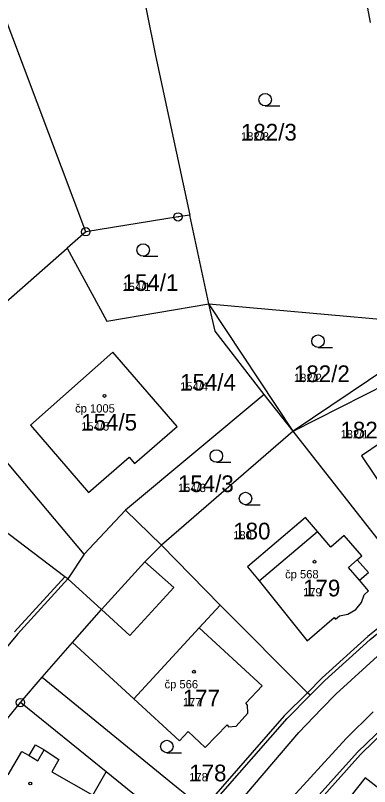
# Model space of a CAD drawing. Extents: x -763628 to -761565, y -976033 to -973833.
# Drawn here: x -762655.5 to -762613, y -974691 to -974598.6 of the extents above; entities that cross this region are included whole.
import ezdxf

# ---------------------------------------------------------------- set-up
doc = ezdxf.new("R2010")
doc.units = 0
for name, color, linetype in [('KN_cisla parcel 1000', 7, 'Continuous'), ('KN_cisla parcel 500', 7, 'Continuous'), ('KN_cisla popisna 500', 7, 'Continuous'), ('KN_hranice parcel', 7, 'Continuous'), ('KN_vnitrni kresba parcel', 7, 'Continuous'), ('KN_znacky bodu BP', 7, 'Continuous'), ('KN_znacky budov', 7, 'Continuous'), ('KN_znacky kultur', 7, 'Continuous')]:
    doc.layers.add(name, color=color, linetype=linetype)

msp = doc.modelspace()

# ---------------------------------------------------------------- linework, layer by layer
at = {"layer": 'KN_hranice parcel'}
for p, q in [((-762612.91, -974599.43), (-762618.76, -974568.2)), ((-762632.29, -974633.14), (-762634.57, -974622.51)), ((-762647.05, -974624.52), (-762649.29, -974626.49)), ((-762665.72, -974640.94), (-762649.29, -974626.49)), ((-762632.29, -974633.14), (-762603.39, -974635.73)), ((-762603.39, -974635.73), (-762622.2, -974648.42)), ((-762625.65, -974644.02), (-762642.29, -974657.86)), ((-762622.2, -974648.42), (-762625.65, -974644.02)), ((-762622.2, -974648.42), (-762637.97, -974662.06)), ((-762642.29, -974657.86), (-762647.23, -974663.13)), ((-762637.97, -974662.06), (-762642.29, -974657.86)), ((-762630.95, -974669.27), (-762637.97, -974662.06)), ((-762645.18, -974669.79), (-762649.21, -974666.12)), ((-762648.64, -974673.74), (-762645.18, -974669.79)), ((-762652.27, -974677.87), (-762648.64, -974673.74)), ((-762654.88, -974680.93), (-762652.27, -974677.87)), ((-762644.62, -974689.22), (-762654.88, -974680.93))]:
    msp.add_line(p, q, dxfattribs=at)
for points in [[(-762647.05, -974624.52), (-762657.34, -974597.25), (-762662.48, -974563.76)], [(-762618.76, -974568.2), (-762645.99, -974567.07), (-762638.7, -974603.41), (-762634.57, -974622.51)], [(-762634.57, -974622.51), (-762635.99, -974622.74), (-762647.05, -974624.52)], [(-762649.29, -974626.49), (-762644.53, -974635.22), (-762632.29, -974633.14)], [(-762625.65, -974644.02), (-762631.55, -974636.43), (-762632.29, -974633.14)], [(-762636.09, -974647.87), (-762643.79, -974638.96), (-762653.69, -974647.7), (-762646.7, -974655.78), (-762641.85, -974651.53), (-762641.2, -974652.28), (-762636.09, -974647.87)], [(-762647.23, -974663.13), (-762660.66, -974647.23), (-762665.72, -974640.94)], [(-762606.68, -974662.23), (-762604.57, -974660.79), (-762596.89, -974655.53), (-762599.81, -974651.16), (-762600.1, -974651.38), (-762604.11, -974645.61), (-762604.55, -974644.98), (-762613.98, -974651.38), (-762606.68, -974662.23)], [(-762649.21, -974666.12), (-762649.57, -974665.85), (-762673.44, -974647.74)], [(-762606.66, -974668.22), (-762606.94, -974667.88), (-762622.2, -974648.42)], [(-762619.26, -974660.44), (-762620.72, -974658.76), (-762627.64, -974664.67), (-762626.28, -974666.35), (-762620.5, -974673.52), (-762617.28, -974670.72), (-762617.12, -974670.92), (-762616.64, -974670.52), (-762615.65, -974670.32), (-762614.69, -974669.78), (-762613.98, -974668.93), (-762613.68, -974668.01), (-762613.14, -974667.53), (-762614.23, -974666.27), (-762613.17, -974665.35), (-762614.52, -974663.83), (-762613.97, -974663.36), (-762616.06, -974660.93), (-762617.68, -974662.3), (-762619.26, -974660.44)], [(-762637.97, -974662.06), (-762639.95, -974664.06), (-762645.18, -974669.79)], [(-762649.21, -974666.12), (-762655.24, -974672.73), (-762660.27, -974678.77), (-762663, -974682.24), (-762665.27, -974685.45)], [(-762620.14, -974680.06), (-762618.39, -974678.28), (-762612.95, -974673.38), (-762606.66, -974668.22)], [(-762648.64, -974673.74), (-762641.28, -974680.5), (-762635.82, -974685.52), (-762634.77, -974684.38), (-762632.73, -974686.32), (-762630.11, -974683.59), (-762629.92, -974683.82), (-762629, -974683.77), (-762627.61, -974682.22), (-762627.65, -974681.26), (-762627.84, -974681.02), (-762625.91, -974678.92), (-762633.44, -974671.98), (-762630.95, -974669.27)], [(-762620.14, -974680.06), (-762620.46, -974679.75), (-762630.95, -974669.27)], [(-762652.27, -974677.87), (-762636.16, -974691.01), (-762632.97, -974693.6), (-762632.63, -974693.89)], [(-762605.69, -974678.87), (-762611.21, -974683.7), (-762614.46, -974686.87), (-762623.69, -974697.16), (-762623.68, -974697.83), (-762623.61, -974701.35)], [(-762632.63, -974693.89), (-762622.92, -974682.83), (-762620.14, -974680.06)], [(-762663.53, -974693.31), (-762659.99, -974687.45), (-762657.52, -974684.12), (-762654.88, -974680.93)], [(-762663.53, -974693.31), (-762659.81, -974695.49), (-762651.09, -974700.6), (-762646.21, -974692.01), (-762644.62, -974689.22)], [(-762635.08, -974696.93), (-762635.43, -974696.65), (-762638.63, -974694.06), (-762644.62, -974689.22)], [(-762596.51, -974689.85), (-762600.44, -974694.72), (-762601.76, -974696.35), (-762603.78, -974694.73), (-762608.43, -974691), (-762610.68, -974689.21), (-762612.13, -974691.07), (-762613.56, -974689.95), (-762618.28, -974695.91), (-762616.8, -974697.06), (-762618.25, -974698.92), (-762611.55, -974704.32), (-762609.59, -974705.89), (-762612.75, -974709.74)]]:
    msp.add_lwpolyline(points, dxfattribs=at)
at = {"layer": 'KN_vnitrni kresba parcel'}
for p, q in [((-762622.2, -974648.42), (-762632.29, -974633.14)), ((-762622.2, -974648.42), (-762606.47, -974640.41)), ((-762626.28, -974666.35), (-762619.26, -974660.44)), ((-762647.23, -974663.13), (-762649.21, -974666.12)), ((-762615.56, -974664.73), (-762614.52, -974663.83)), ((-762636.5, -974667.15), (-762639.95, -974664.06)), ((-762614.23, -974666.27), (-762615.56, -974664.73)), ((-762655.58, -974672.44), (-762649.57, -974665.85)), ((-762641.77, -974672.91), (-762636.5, -974667.15)), ((-762606.94, -974667.88), (-762613.23, -974673.03)), ((-762645.18, -974669.79), (-762641.77, -974672.91)), ((-762641.28, -974680.5), (-762633.44, -974671.98)), ((-762613.23, -974673.03), (-762618.71, -974677.96)), ((-762617.03, -974679.9), (-762611.62, -974674.97)), ((-762618.71, -974677.96), (-762620.46, -974679.75)), ((-762620.46, -974679.75), (-762623.26, -974682.53)), ((-762618.78, -974681.69), (-762617.03, -974679.9)), ((-762621.52, -974684.5), (-762618.78, -974681.69)), ((-762615.82, -974685.23), (-762612.58, -974682.05)), ((-762623.26, -974682.53), (-762632.97, -974693.6)), ((-762614.13, -974687.17), (-762610.91, -974684.04)), ((-762630.81, -974695.4), (-762621.52, -974684.5)), ((-762625.17, -974695.39), (-762615.82, -974685.23)), ((-762653.83, -974687.29), (-762653.06, -974685.98)), ((-762653.06, -974685.98), (-762652.02, -974686.6)), ((-762656.35, -974689.59), (-762654.7, -974686.78)), ((-762654.7, -974686.78), (-762653.83, -974687.29)), ((-762652.78, -974687.9), (-762652.02, -974686.6)), ((-762652.02, -974686.6), (-762650.26, -974687.76)), ((-762653.83, -974687.29), (-762652.78, -974687.9)), ((-762650.26, -974687.76), (-762651.1, -974689.23)), ((-762623.68, -974697.83), (-762614.13, -974687.17)), ((-762651.1, -974689.23), (-762646.21, -974692.01))]:
    msp.add_line(p, q, dxfattribs=at)
at = {"layer": 'KN_znacky bodu BP'}
for centre, radius in [((-762635.99, -974622.74), 0.5), ((-762635.99, -974622.74), 0.0303), ((-762647.05, -974624.52), 0.5), ((-762647.05, -974624.52), 0.0303), ((-762654.88, -974680.93), 0.5), ((-762654.88, -974680.93), 0.0303)]:
    msp.add_circle(centre, radius, dxfattribs=at)
at = {"layer": 'KN_znacky budov'}
for centre in [(-762644.797, -974644.189), (-762619.627, -974664.059), (-762634.077, -974677.239), (-762653.697, -974690.629)]:
    msp.add_circle(centre, 0.175, dxfattribs=at)
at = {"layer": 'KN_znacky kultur'}
for p, q in [((-762625.543, -974609.44), (-762623.793, -974609.44)), ((-762640.173, -974627.46), (-762638.423, -974627.46)), ((-762619.203, -974638.38), (-762617.453, -974638.38)), ((-762631.393, -974652.13), (-762629.643, -974652.13)), ((-762627.903, -974657.23), (-762626.153, -974657.23)), ((-762637.333, -974686.94), (-762635.583, -974686.94))]:
    msp.add_line(p, q, dxfattribs=at)
for centre in [(-762625.543, -974608.69), (-762640.173, -974626.71), (-762619.203, -974637.63), (-762631.393, -974651.38), (-762627.903, -974656.48), (-762637.333, -974686.19)]:
    msp.add_circle(centre, 0.75, dxfattribs=at)

# ---------------------------------------------------------------- texts
at = {"layer": 'KN_cisla parcel 1000'}
for s, p in [('182/3', (-762628.44, -974613.59)), ('154/1', (-762642.64, -974631.61)), ('182/2', (-762622.09, -974642.53)), ('154/4', (-762635.74, -974643.55)), ('154/5', (-762647.59, -974648.34)), ('182/1', (-762616.51, -974649.28)), ('154/3', (-762636, -974655.71)), ('180', (-762629.37, -974661.38)), ('179', (-762621, -974668.21)), ('177', (-762635.42, -974681.39)), ('178', (-762634.64, -974690.37))]:
    msp.add_text(s, height=2, dxfattribs=at).set_placement(p)
at = {"layer": 'KN_cisla parcel 500'}
for s, p in [('182/3', (-762628.44, -974613.59)), ('154/1', (-762642.64, -974631.61)), ('182/2', (-762622.09, -974642.53)), ('154/4', (-762635.74, -974643.55)), ('154/5', (-762647.59, -974648.34)), ('182/1', (-762616.51, -974649.28)), ('154/3', (-762636, -974655.71)), ('180', (-762629.37, -974661.38)), ('179', (-762621, -974668.21)), ('177', (-762635.42, -974681.39)), ('178', (-762634.64, -974690.37))]:
    msp.add_text(s, height=1, dxfattribs=at).set_placement(p)
at = {"layer": 'KN_cisla popisna 500'}
for s, p in [('čp 1005', (-762648.321, -974646.181)), ('čp 568', (-762623.151, -974666.051)), ('čp 566', (-762637.601, -974679.231))]:
    msp.add_text(s, height=1, dxfattribs=at).set_placement(p)

doc.saveas('drawing.dxf')
